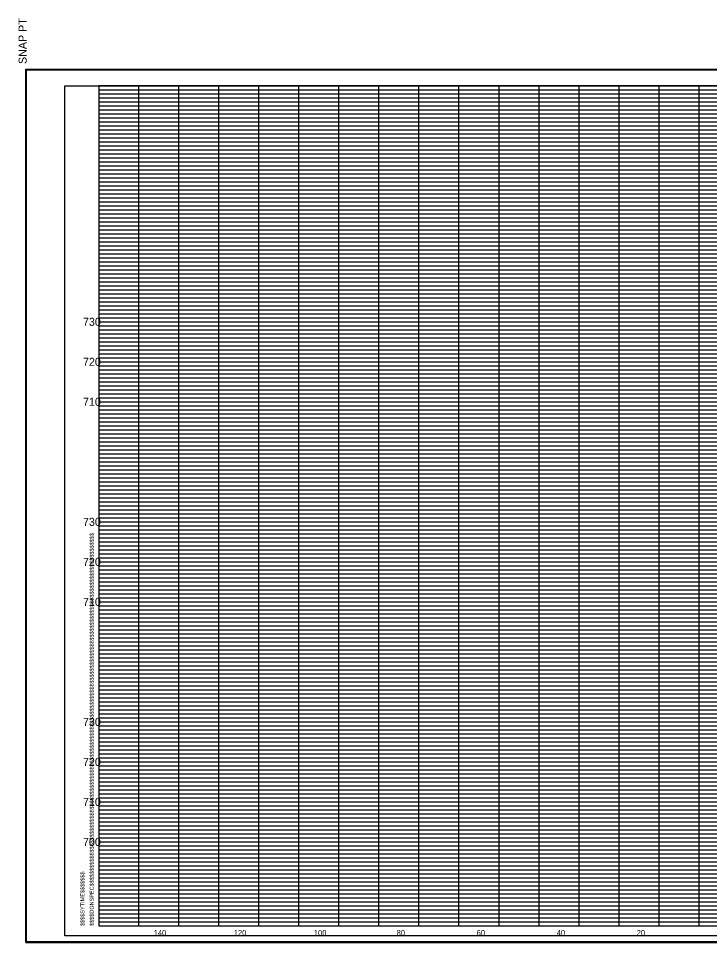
# Model space of a CAD drawing. Extents: x -200 to 1704, y -325 to 2307.
# Drawn here: x 979.9 to 1152.6, y 995.9 to 1226.8 of the extents above; entities that cross this region are included whole.
import ezdxf

# ---------------------------------------------------------------- set-up
doc = ezdxf.new("R2010")
doc.units = 0
for name, color, linetype in [('DESIGN - SHEET - Corner Text', 7, 'Continuous'), ('DESIGN - SHEET - Light Grid', 7, 'Continuous'), ('DESIGN - SHEET - Linework', 7, 'Continuous'), ('DESIGN - SHEET - Plot Shape', 7, 'Continuous'), ('DESIGN - TYPICAL - Text', 7, 'Continuous')]:
    doc.layers.add(name, color=color, linetype=linetype)

msp = doc.modelspace()

# ---------------------------------------------------------------- linework, layer by layer
at = {"layer": 'DESIGN - SHEET - Light Grid'}
for p, q in [((1000, 1209), (1080, 1209)), ((1000, 1208), (1080, 1208)), ((1080, 1209), (1160, 1209)), ((1080, 1208), (1160, 1208)), ((1000, 1207), (1080, 1207)), ((1000, 1206), (1080, 1206)), ((1080, 1207), (1160, 1207)), ((1080, 1206), (1160, 1206)), ((1000, 1205), (1080, 1205)), ((1000, 1204), (1080, 1204)), ((1080, 1205), (1160, 1205)), ((1080, 1204), (1160, 1204)), ((1000, 1203), (1080, 1203)), ((1000, 1202), (1080, 1202)), ((1000, 1201), (1080, 1201)), ((1080, 1203), (1160, 1203)), ((1080, 1202), (1160, 1202)), ((1080, 1201), (1160, 1201)), ((1000, 1199), (1080, 1199)), ((1080, 1199), (1160, 1199)), ((1000, 1198), (1080, 1198)), ((1000, 1197), (1080, 1197)), ((1080, 1198), (1160, 1198)), ((1080, 1197), (1160, 1197)), ((1000, 1196), (1080, 1196)), ((1000, 1195), (1080, 1195)), ((1080, 1196), (1160, 1196)), ((1080, 1195), (1160, 1195)), ((1000, 1194), (1080, 1194)), ((1000, 1193), (1080, 1193)), ((1000, 1192), (1080, 1192)), ((1080, 1194), (1160, 1194)), ((1080, 1193), (1160, 1193)), ((1080, 1192), (1160, 1192)), ((1000, 1191), (1080, 1191)), ((1080, 1191), (1160, 1191)), ((1000, 1189), (1080, 1189)), ((1000, 1188), (1080, 1188)), ((1080, 1189), (1160, 1189)), ((1080, 1188), (1160, 1188)), ((1000, 1187), (1080, 1187)), ((1000, 1186), (1080, 1186)), ((1000, 1185), (1080, 1185)), ((1080, 1187), (1160, 1187)), ((1080, 1186), (1160, 1186)), ((1080, 1185), (1160, 1185)), ((1000, 1184), (1080, 1184)), ((1000, 1183), (1080, 1183)), ((1080, 1184), (1160, 1184)), ((1080, 1183), (1160, 1183)), ((1000, 1182), (1080, 1182)), ((1000, 1181), (1080, 1181)), ((1080, 1182), (1160, 1182)), ((1080, 1181), (1160, 1181)), ((1000, 1179), (1080, 1179)), ((1000, 1178), (1080, 1178)), ((1080, 1179), (1160, 1179)), ((1080, 1178), (1160, 1178)), ((1000, 1177), (1080, 1177)), ((1000, 1176), (1080, 1176)), ((1080, 1177), (1160, 1177)), ((1080, 1176), (1160, 1176)), ((1000, 1175), (1080, 1175)), ((1000, 1174), (1080, 1174)), ((1080, 1175), (1160, 1175)), ((1080, 1174), (1160, 1174)), ((1000, 1173), (1080, 1173)), ((1000, 1172), (1080, 1172)), ((1000, 1171), (1080, 1171)), ((1080, 1173), (1160, 1173)), ((1080, 1172), (1160, 1172)), ((1080, 1171), (1160, 1171)), ((1000, 1169), (1080, 1169)), ((1080, 1169), (1160, 1169)), ((1000, 1168), (1080, 1168)), ((1000, 1167), (1080, 1167)), ((1080, 1168), (1160, 1168)), ((1080, 1167), (1160, 1167)), ((1000, 1166), (1080, 1166)), ((1000, 1165), (1080, 1165)), ((1000, 1164), (1080, 1164)), ((1080, 1166), (1160, 1166)), ((1080, 1165), (1160, 1165)), ((1080, 1164), (1160, 1164)), ((1000, 1163), (1080, 1163)), ((1000, 1162), (1080, 1162)), ((1080, 1163), (1160, 1163)), ((1080, 1162), (1160, 1162)), ((1000, 1161), (1080, 1161)), ((1080, 1161), (1160, 1161)), ((1000, 1159), (1080, 1159)), ((1000, 1158), (1080, 1158)), ((1080, 1159), (1160, 1159)), ((1080, 1158), (1160, 1158)), ((1000, 1157), (1080, 1157)), ((1000, 1156), (1080, 1156)), ((1000, 1155), (1080, 1155)), ((1080, 1157), (1160, 1157)), ((1080, 1156), (1160, 1156)), ((1080, 1155), (1160, 1155)), ((1000, 1154), (1080, 1154)), ((1000, 1153), (1080, 1153)), ((1080, 1154), (1160, 1154)), ((1080, 1153), (1160, 1153)), ((1000, 1152), (1080, 1152)), ((1000, 1151), (1080, 1151)), ((1080, 1152), (1160, 1152)), ((1080, 1151), (1160, 1151)), ((1000, 1149), (1080, 1149)), ((1000, 1148), (1080, 1148)), ((1080, 1149), (1160, 1149)), ((1080, 1148), (1160, 1148)), ((1000, 1147), (1080, 1147)), ((1000, 1146), (1080, 1146)), ((1080, 1147), (1160, 1147)), ((1080, 1146), (1160, 1146)), ((1000, 1145), (1080, 1145)), ((1000, 1144), (1080, 1144)), ((1080, 1145), (1160, 1145)), ((1080, 1144), (1160, 1144)), ((1000, 1143), (1080, 1143)), ((1000, 1142), (1080, 1142)), ((1000, 1141), (1080, 1141)), ((1080, 1143), (1160, 1143)), ((1080, 1142), (1160, 1142)), ((1080, 1141), (1160, 1141)), ((1000, 1139), (1080, 1139)), ((1080, 1139), (1160, 1139)), ((1000, 1138), (1080, 1138)), ((1000, 1137), (1080, 1137)), ((1080, 1138), (1160, 1138)), ((1080, 1137), (1160, 1137)), ((1000, 1136), (1080, 1136)), ((1000, 1135), (1080, 1135)), ((1000, 1134), (1080, 1134)), ((1080, 1136), (1160, 1136)), ((1080, 1135), (1160, 1135)), ((1080, 1134), (1160, 1134)), ((1000, 1133), (1080, 1133)), ((1000, 1132), (1080, 1132)), ((1080, 1133), (1160, 1133)), ((1080, 1132), (1160, 1132)), ((1000, 1131), (1080, 1131)), ((1080, 1131), (1160, 1131)), ((1000, 1129), (1080, 1129)), ((1000, 1128), (1080, 1128)), ((1080, 1129), (1160, 1129)), ((1080, 1128), (1160, 1128)), ((1000, 1127), (1080, 1127)), ((1000, 1126), (1080, 1126)), ((1000, 1125), (1080, 1125)), ((1080, 1127), (1160, 1127)), ((1080, 1126), (1160, 1126)), ((1080, 1125), (1160, 1125)), ((1000, 1124), (1080, 1124)), ((1000, 1123), (1080, 1123)), ((1080, 1124), (1160, 1124)), ((1080, 1123), (1160, 1123)), ((1000, 1122), (1080, 1122)), ((1000, 1121), (1080, 1121)), ((1080, 1122), (1160, 1122)), ((1080, 1121), (1160, 1121)), ((1000, 1119), (1080, 1119)), ((1000, 1118), (1080, 1118)), ((1080, 1119), (1160, 1119)), ((1080, 1118), (1160, 1118)), ((1000, 1117), (1080, 1117)), ((1000, 1116), (1080, 1116)), ((1080, 1117), (1160, 1117)), ((1080, 1116), (1160, 1116)), ((1000, 1115), (1080, 1115)), ((1000, 1114), (1080, 1114)), ((1080, 1115), (1160, 1115)), ((1080, 1114), (1160, 1114)), ((1000, 1113), (1080, 1113)), ((1000, 1112), (1080, 1112)), ((1000, 1111), (1080, 1111)), ((1080, 1113), (1160, 1113)), ((1080, 1112), (1160, 1112)), ((1080, 1111), (1160, 1111)), ((1000, 1109), (1080, 1109)), ((1080, 1109), (1160, 1109)), ((1000, 1108), (1080, 1108)), ((1000, 1107), (1080, 1107)), ((1080, 1108), (1160, 1108)), ((1080, 1107), (1160, 1107)), ((1000, 1106), (1080, 1106)), ((1000, 1105), (1080, 1105)), ((1000, 1104), (1080, 1104)), ((1080, 1106), (1160, 1106)), ((1080, 1105), (1160, 1105)), ((1080, 1104), (1160, 1104)), ((1000, 1103), (1080, 1103)), ((1000, 1102), (1080, 1102)), ((1080, 1103), (1160, 1103)), ((1080, 1102), (1160, 1102)), ((1000, 1101), (1080, 1101)), ((1080, 1101), (1160, 1101)), ((1000, 1099), (1080, 1099)), ((1000, 1098), (1080, 1098)), ((1080, 1099), (1160, 1099)), ((1080, 1098), (1160, 1098)), ((1000, 1097), (1080, 1097)), ((1000, 1096), (1080, 1096)), ((1000, 1095), (1080, 1095)), ((1080, 1097), (1160, 1097)), ((1080, 1096), (1160, 1096)), ((1080, 1095), (1160, 1095)), ((1000, 1094), (1080, 1094)), ((1000, 1093), (1080, 1093)), ((1080, 1094), (1160, 1094)), ((1080, 1093), (1160, 1093)), ((1000, 1092), (1080, 1092)), ((1000, 1091), (1080, 1091)), ((1080, 1092), (1160, 1092)), ((1080, 1091), (1160, 1091)), ((1000, 1089), (1080, 1089)), ((1000, 1088), (1080, 1088)), ((1080, 1089), (1160, 1089)), ((1080, 1088), (1160, 1088)), ((1000, 1087), (1080, 1087)), ((1000, 1086), (1080, 1086)), ((1080, 1087), (1160, 1087)), ((1080, 1086), (1160, 1086)), ((1000, 1085), (1080, 1085)), ((1000, 1084), (1080, 1084)), ((1080, 1085), (1160, 1085)), ((1080, 1084), (1160, 1084)), ((1000, 1083), (1080, 1083)), ((1000, 1082), (1080, 1082)), ((1000, 1081), (1080, 1081)), ((1080, 1083), (1160, 1083)), ((1080, 1082), (1160, 1082)), ((1080, 1081), (1160, 1081)), ((1000, 1079), (1080, 1079)), ((1080, 1079), (1160, 1079)), ((1000, 1078), (1080, 1078)), ((1000, 1077), (1080, 1077)), ((1080, 1078), (1160, 1078)), ((1080, 1077), (1160, 1077)), ((1000, 1076), (1080, 1076)), ((1000, 1075), (1080, 1075)), ((1000, 1074), (1080, 1074)), ((1080, 1076), (1160, 1076)), ((1080, 1075), (1160, 1075)), ((1080, 1074), (1160, 1074)), ((1000, 1073), (1080, 1073)), ((1000, 1072), (1080, 1072)), ((1080, 1073), (1160, 1073)), ((1080, 1072), (1160, 1072)), ((1000, 1071), (1080, 1071)), ((1080, 1071), (1160, 1071)), ((1000, 1069), (1080, 1069)), ((1000, 1068), (1080, 1068)), ((1000, 1067), (1080, 1067)), ((1080, 1069), (1160, 1069)), ((1080, 1068), (1160, 1068)), ((1080, 1067), (1160, 1067)), ((1000, 1066), (1080, 1066)), ((1000, 1065), (1080, 1065)), ((1080, 1066), (1160, 1066)), ((1080, 1065), (1160, 1065)), ((1000, 1064), (1080, 1064)), ((1000, 1063), (1080, 1063)), ((1080, 1064), (1160, 1064)), ((1080, 1063), (1160, 1063)), ((1000, 1062), (1080, 1062)), ((1000, 1061), (1080, 1061)), ((1080, 1062), (1160, 1062)), ((1080, 1061), (1160, 1061)), ((1000, 1059), (1080, 1059)), ((1000, 1058), (1080, 1058)), ((1080, 1059), (1160, 1059)), ((1080, 1058), (1160, 1058)), ((1000, 1057), (1080, 1057)), ((1000, 1056), (1080, 1056)), ((1080, 1057), (1160, 1057)), ((1080, 1056), (1160, 1056)), ((1000, 1055), (1080, 1055)), ((1000, 1054), (1080, 1054)), ((1080, 1055), (1160, 1055)), ((1080, 1054), (1160, 1054)), ((1000, 1053), (1080, 1053)), ((1000, 1052), (1080, 1052)), ((1000, 1051), (1080, 1051)), ((1080, 1053), (1160, 1053)), ((1080, 1052), (1160, 1052)), ((1080, 1051), (1160, 1051)), ((1000, 1049), (1080, 1049)), ((1080, 1049), (1160, 1049)), ((1000, 1048), (1080, 1048)), ((1000, 1047), (1080, 1047)), ((1080, 1048), (1160, 1048)), ((1080, 1047), (1160, 1047)), ((1000, 1046), (1080, 1046)), ((1000, 1045), (1080, 1045)), ((1000, 1044), (1080, 1044)), ((1080, 1046), (1160, 1046)), ((1080, 1045), (1160, 1045)), ((1080, 1044), (1160, 1044)), ((1000, 1043), (1080, 1043)), ((1000, 1042), (1080, 1042)), ((1080, 1043), (1160, 1043)), ((1080, 1042), (1160, 1042)), ((1000, 1041), (1080, 1041)), ((1080, 1041), (1160, 1041)), ((1000, 1039), (1080, 1039)), ((1000, 1038), (1080, 1038)), ((1000, 1037), (1080, 1037)), ((1080, 1039), (1160, 1039)), ((1080, 1038), (1160, 1038)), ((1080, 1037), (1160, 1037)), ((1000, 1036), (1080, 1036)), ((1000, 1035), (1080, 1035)), ((1080, 1036), (1160, 1036)), ((1080, 1035), (1160, 1035)), ((1000, 1034), (1080, 1034)), ((1000, 1033), (1080, 1033)), ((1080, 1034), (1160, 1034)), ((1080, 1033), (1160, 1033)), ((1000, 1032), (1080, 1032)), ((1000, 1031), (1080, 1031)), ((1080, 1032), (1160, 1032)), ((1080, 1031), (1160, 1031)), ((1000, 1029), (1080, 1029)), ((1000, 1028), (1080, 1028)), ((1080, 1029), (1160, 1029)), ((1080, 1028), (1160, 1028)), ((1000, 1027), (1080, 1027)), ((1000, 1026), (1080, 1026)), ((1080, 1027), (1160, 1027)), ((1080, 1026), (1160, 1026)), ((1000, 1025), (1080, 1025)), ((1000, 1024), (1080, 1024)), ((1080, 1025), (1160, 1025)), ((1080, 1024), (1160, 1024)), ((1000, 1023), (1080, 1023)), ((1000, 1022), (1080, 1022)), ((1000, 1021), (1080, 1021)), ((1080, 1023), (1160, 1023)), ((1080, 1022), (1160, 1022)), ((1080, 1021), (1160, 1021)), ((1000, 1019), (1080, 1019)), ((1080, 1019), (1160, 1019)), ((1000, 1018), (1080, 1018)), ((1000, 1017), (1080, 1017)), ((1080, 1018), (1160, 1018)), ((1080, 1017), (1160, 1017)), ((1000, 1016), (1080, 1016)), ((1000, 1015), (1080, 1015)), ((1000, 1014), (1080, 1014)), ((1080, 1016), (1160, 1016)), ((1080, 1015), (1160, 1015)), ((1080, 1014), (1160, 1014)), ((1000, 1013), (1080, 1013)), ((1000, 1012), (1080, 1012)), ((1080, 1013), (1160, 1013)), ((1080, 1012), (1160, 1012)), ((1000, 1011), (1080, 1011)), ((1080, 1011), (1160, 1011)), ((1000, 1009), (1080, 1009)), ((1000, 1008), (1080, 1008)), ((1000, 1007), (1080, 1007)), ((1080, 1009), (1160, 1009)), ((1080, 1008), (1160, 1008)), ((1080, 1007), (1160, 1007)), ((1000, 1006), (1080, 1006)), ((1000, 1005), (1080, 1005)), ((1080, 1006), (1160, 1006)), ((1080, 1005), (1160, 1005)), ((1000, 1004), (1080, 1004)), ((1000, 1003), (1080, 1003)), ((1080, 1004), (1160, 1004)), ((1080, 1003), (1160, 1003)), ((1000, 1002), (1080, 1002)), ((1000, 1001), (1080, 1001)), ((1080, 1002), (1160, 1002)), ((1080, 1001), (1160, 1001))]:
    msp.add_line(p, q, dxfattribs=at)
at = {"layer": 'DESIGN - SHEET - Linework'}
for p, q in [((981.77, 995.86), (981.77, 1214.14)), ((981.77, 1214.14), (1322.17, 1214.14)), ((1010, 1000), (1010, 1210)), ((1020, 1000), (1020, 1210)), ((1030, 1000), (1030, 1210)), ((1040, 1000), (1040, 1210)), ((1050, 1000), (1050, 1210)), ((1060, 1000), (1060, 1210)), ((1070, 1000), (1070, 1210)), ((1080, 1000), (1080, 1210)), ((1090, 1000), (1090, 1210)), ((1100, 1000), (1100, 1210)), ((1110, 1000), (1110, 1210)), ((1120, 1000), (1120, 1210)), ((1130, 1000), (1130, 1210)), ((1140, 1000), (1140, 1210)), ((1150, 1000), (1150, 1210)), ((1000, 1200), (1280, 1200)), ((1000, 1190), (1320, 1190)), ((1000, 1180), (1320, 1180)), ((1000, 1170), (1320, 1170)), ((1000, 1160), (1320, 1160)), ((1000, 1150), (1320, 1150)), ((1000, 1140), (1320, 1140)), ((1000, 1130), (1320, 1130)), ((1000, 1120), (1320, 1120)), ((1000, 1110), (1320, 1110)), ((1000, 1100), (1320, 1100)), ((1000, 1090), (1320, 1090)), ((1000, 1080), (1320, 1080)), ((1000, 1070), (1320, 1070)), ((1000, 1060), (1320, 1060)), ((1000, 1050), (1320, 1050)), ((1000, 1040), (1320, 1040)), ((1000, 1030), (1320, 1030)), ((1000, 1020), (1320, 1020)), ((1000, 1010), (1320, 1010)), ((981.77, 995.86), (1322.17, 995.86))]:
    msp.add_line(p, q, dxfattribs=at)
msp.add_lwpolyline([(1000, 1210), (1000, 1000), (1320, 1000), (1320, 1210), (1000, 1210)], dxfattribs=at)
at = {"layer": 'DESIGN - SHEET - Plot Shape'}
for points in [[(981.97, 1213.94), (1321.97, 1213.94), (1321.97, 996.06), (981.97, 996.06)], [(991.5, 1210), (1320, 1210), (1320, 997.5), (991.5, 997.5)]]:
    msp.add_lwpolyline(points, close=True, dxfattribs=at)

# ---------------------------------------------------------------- texts
at = {"layer": 'DESIGN - SHEET - Corner Text'}
for s, height, p in [('  SNAP PT', 2, (981.97, 1213.94)), ('$$$$DGNSPEC$$$$$$$$$$$$$$$$$$$$$$$$$$$$$$$$$$$$$$$$$$$$$$$$$$$$$$$$$$$$$$$$$$$$$$$$$$$$$$$$$$$$$$$$$$$$$$$$$$$$$$$$$$$$$$$$$$$', 1.00002, (998.74, 1000)), ('$$$$SYTIME$$$$$$$', 1, (996.42, 1000))]:
    msp.add_text(s, height=height, rotation=90, dxfattribs=at).set_placement(p)
at = {"layer": 'DESIGN - TYPICAL - Text'}
for s, height, p in [('     730     ', 2, (992.34, 1150)), ('     720     ', 2, (992.34, 1140)), ('     710     ', 2, (992.34, 1130)), ('     730     ', 2, (992.34, 1100)), ('     720     ', 2, (992.34, 1090)), ('     710     ', 2, (992.34, 1080)), ('     730     ', 2, (992.34, 1050)), ('     720     ', 2, (992.34, 1040)), ('     710     ', 2, (992.34, 1030)), ('     700     ', 2, (992.34, 1020)), ('     140     ', 1.4, (1011.14, 997.6)), ('     120     ', 1.4, (1031.14, 997.6)), ('     100     ', 1.4, (1051.14, 997.6)), ('     80     ', 1.4, (1071.82, 997.6)), ('     60     ', 1.4, (1091.82, 997.6)), ('     40     ', 1.4, (1111.82, 997.6)), ('     20     ', 1.4, (1131.82, 997.6))]:
    msp.add_text(s, height=height, dxfattribs=at).set_placement(p)

doc.saveas('drawing.dxf')
